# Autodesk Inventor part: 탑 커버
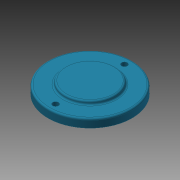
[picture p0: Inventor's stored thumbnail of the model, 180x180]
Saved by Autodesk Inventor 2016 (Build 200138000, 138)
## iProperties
Created: 2017-05
Part Number: 탑 커버
Material: 알루미늄 6061
Document SubType Name: Modeling
Designer: mduedu
Density: 1 g/cm^3
Appearance: 터키옥색
Author: mduedu
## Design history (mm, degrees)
sketch "스케치1"
  geometry: C1 r 25 at (0, 0); 1 further point
  constraints: 1 centre point, 1 coincident
  dimensions: "d31" = 50 diameter of C1
extrude "돌출1" new body sketch "스케치1" distance "d2" = 5; taper "d3" = 0 deg
sketch "스케치2"
  geometry: C1 r 15 at (0, 0); 1 further point
  constraints: 1 centre point, 1 coincident
  dimensions: "d5" = 30 diameter of C1
extrude "돌출2" join sketch "스케치2" distance "d6" = 2; taper "d7" = 0 deg
sketch "스케치3"
  geometry: C1 r 16 at (0, 0); 1 further point
  constraints: 1 centre point, 1 coincident
  dimensions: "d32" = 32 diameter of C1
extrude "돌출3" join sketch "스케치3" distance "d10" = 3; taper "d11" = 0 deg
sketch "스케치4"
  geometry: C1 r 16 at (0, 0) reference; C2 r 14 at (0, 0); 1 further point
  constraints: 1 centre point
  dimensions: "d33" = 2 radial gap between concentric circles of C2 C1
extrude "돌출4" cut sketch "스케치4" distance "d14" = 6; taper "d15" = 0 deg
chamfer "모따기1" distance "d16" = 1; stored, may be unused: second distance "d17" = 2, angle "d18" = 45 deg
fillet "모깎기3" dims "d19" = 1
fillet "모깎기4" dims "d20" = 1
fillet "모깎기5" dims "d21" = 1
sketch "스케치5" dims "d34" = 41
  geometry: C1 r 25 at (0, 0) reference; 2 further points
  constraints: 2 vertical alignment, 1 coincident, 2 other
hole "구멍2" sketch "스케치5" at (0, 20.5) diameter "d35" = 3.4; stored, may be unused: countersink angle "d39" = 90 deg, drill point angle "d41" = 118 deg; dims "d36" = 6, "d37" = 4, "d38" = 2, "d40" = 8
node "솔리드1"
pattern_circular "원형 패턴1" dims angle "d43" = 360 deg
node "투영된 루프2"
